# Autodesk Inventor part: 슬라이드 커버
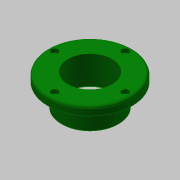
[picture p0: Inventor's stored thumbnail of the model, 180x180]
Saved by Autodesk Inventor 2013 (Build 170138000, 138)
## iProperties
Created: 2015-10
Part Number: 슬라이드 커버
Document SubType Name: Modeling
Designer: mdu
Density: 7.86 g/cm^3
Material: 알루미늄 6061
Mass: 598.523 g
Surface Area: 229.996 cm^2
Volume: 76.148 cm^3
Author: mdu
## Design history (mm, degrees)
sketch "스케치1"
  geometry: C1 r 47.5 at (0, 0); C2 r 32.5 at (0, 0); 1 further point
  constraints: 2 centre point, 2 coincident
  dimensions: "d33" = 95 diameter of C1; "d35" = 65 diameter of C2
extrude "돌출1" new body sketch "스케치1" distance "d0" = 10; taper "d1" = 0 deg
extrude "돌출2" join sketch "스케치1" distance "d2" = 26; taper "d3" = 0 deg
hole "구멍1" diameter "d6" = 50; stored, may be unused: countersink angle "d10" = 90 deg, drill point angle "d12" = 118 deg; dims "d4" = 10, "d5" = 10, "d7" = 6, "d8" = 4, "d9" = 2, "d11" = 8
sketch "스케치2" dims "d36" = 80
  geometry: 4 further points
  constraints: 2 coincident, 2 vertical alignment, 2 other
hole "구멍2" sketch "스케치2" at (0, 40) diameter "d13" = 4.5; stored, may be unused: countersink angle "d17" = 90 deg, drill point angle "d19" = 118 deg; dims "d14" = 6, "d15" = 8, "d16" = 4.4, "d18" = 8
fillet "모깎기1" dims "d23" = 3
chamfer "모따기1" distance "d24" = 1; stored, may be unused: second distance "d25" = 2, angle "d26" = 45 deg
sketch "스케치3"
  geometry: C1 r 25 at (0, 0); C2 r 30 at (0, 0); C3 r 26 at (0, 0) reference; 1 further point
  constraints: 2 centre point, 2 coincident
  dimensions: "d27" = 60 diameter of C2
extrude "돌출3" cut sketch "스케치3" distance "d28" = 3; taper "d29" = 0 deg
chamfer "모따기2" distance "d30" = 1; stored, may be unused: second distance "d31" = 2, angle "d32" = 45 deg
node "솔리드1"
pattern_circular "원형 패턴1" dims angle "d21" = 360 deg
